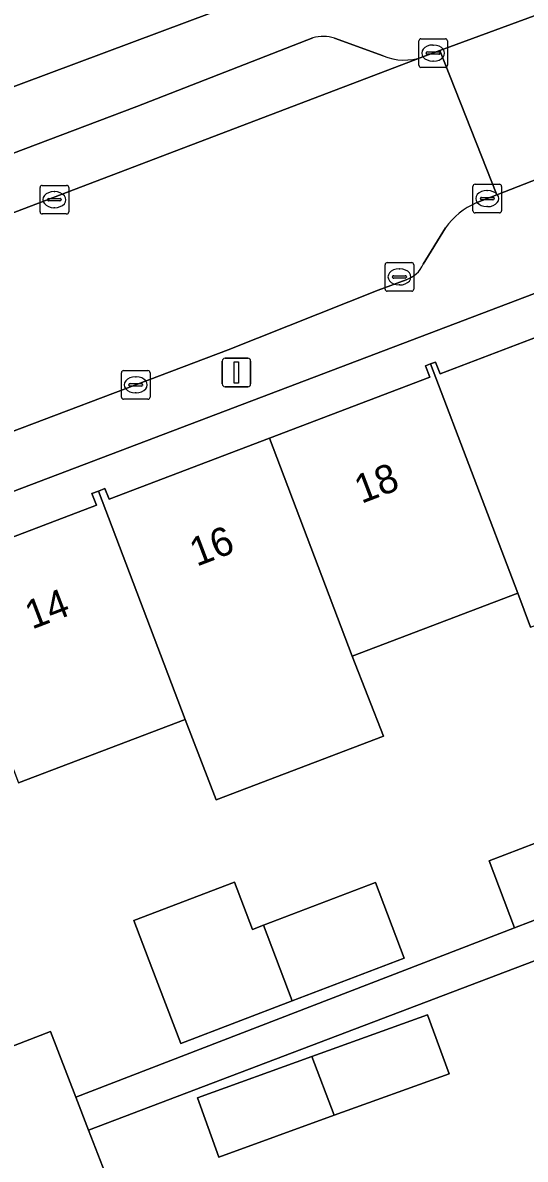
# Model space of a CAD drawing. Extents: x 159262 to 160143, y 383399 to 384319.
# Drawn here: x 159394.93 to 159412.47, y 383870.4 to 383910.07 of the extents above; entities that cross this region are included whole.
import ezdxf

# ---------------------------------------------------------------- set-up
doc = ezdxf.new("R2010")
doc.units = 0
for name, color, linetype in [('IMGEO_Erf', 7, 'Continuous'), ('IMGEO_Kolk', 7, 'Continuous'), ('IMGEO_Lichtmast', 7, 'Continuous'), ('IMGEO_Pand', 7, 'Continuous'), ('IMGEO_Pand_nummerreeks', 7, 'Continuous'), ('IMGEO_Parkeervlak_open', 7, 'Continuous'), ('IMGEO_Rijbaan_lokaal_open', 7, 'Continuous'), ('IMGEO_Voetpad_open', 7, 'Continuous')]:
    doc.layers.add(name, color=color, linetype=linetype)

msp = doc.modelspace()

# ---------------------------------------------------------------- linework, layer by layer
at = {"layer": 'IMGEO_Erf'}
for points in [[(159344.204, 383933.471), (159339.87, 383931.849), (159348.323, 383909.525), (159348.27, 383909.245), (159354.634, 383892.446), (159357.328, 383893.521), (159359.454, 383894.369), (159391.087, 383906.525), (159403.464, 383911.157), (159412.277, 383914.472)], [(159417.717, 383902.495), (159363.447, 383881.885), (159359.686, 383880.457)], [(159391.972, 383873.342), (159395.894, 383874.856), (159396.776, 383872.57), (159412.093, 383878.481), (159411.201, 383880.818), (159415.03, 383882.281), (159414.52, 383883.616), (159420.498, 383885.901), (159421.901, 383882.229), (159426.589, 383884.021), (159421.273, 383900.478)], [(159391.905, 383891.102), (159397.497, 383893.23), (159397.343, 383893.634), (159397.57, 383893.72), (159397.797, 383893.807), (159397.939, 383893.433), (159403.539, 383895.563), (159409.136, 383897.693), (159408.984, 383898.091), (159409.161, 383898.158), (159409.336, 383898.225), (159409.494, 383897.813), (159414.875, 383899.86)], [(159412.653, 383888.968), (159412.203, 383890.152), (159406.429, 383887.958), (159407.518, 383885.163), (159401.676, 383882.943), (159400.601, 383885.744), (159394.782, 383883.533)], [(159433.414, 383862.892), (159427.008, 383882.725), (159397.222, 383871.414), (159397.789, 383869.946), (159393.849, 383868.425)]]:
    msp.add_lwpolyline(points, dxfattribs=at)
for points in [[(159399.434, 383877.085), (159398.808, 383878.731), (159402.319, 383880.066), (159402.945, 383878.42), (159403.329, 383878.566), (159407.235, 383880.052), (159408.24, 383877.411), (159404.333, 383875.925), (159400.439, 383874.443)], [(159405.801, 383871.932), (159401.77, 383870.476), (159401.023, 383872.543), (159405.018, 383873.985), (159409.058, 383875.444), (159409.805, 383873.377)]]:
    msp.add_lwpolyline(points, close=True, dxfattribs=at)
at = {"layer": 'IMGEO_Kolk'}
for p, q in [((159408.75, 383908.582), (159408.75, 383909.434)), ((159408.825, 383909.508), (159409.677, 383909.508)), ((159409.238, 383909.288), (159409.263, 383909.288)), ((159409.751, 383909.434), (159409.751, 383908.582)), ((159409.009, 383909.002), (159409.009, 383909.014)), ((159409.447, 383908.965), (159409.049, 383908.965)), ((159409.052, 383909.051), (159409.45, 383909.051)), ((159409.261, 383908.728), (159409.236, 383908.728)), ((159409.493, 383909.014), (159409.493, 383909.002)), ((159409.677, 383908.508), (159408.825, 383908.508)), ((159395.605, 383904.391), (159396.457, 383904.391)), ((159410.714, 383904.429), (159411.566, 383904.429)), ((159395.53, 383903.465), (159395.53, 383904.317)), ((159396.018, 383904.171), (159396.043, 383904.171)), ((159396.531, 383904.317), (159396.531, 383903.465)), ((159410.639, 383903.503), (159410.639, 383904.355)), ((159410.941, 383903.972), (159411.339, 383903.972)), ((159411.127, 383904.209), (159411.152, 383904.209)), ((159411.64, 383904.355), (159411.64, 383903.503)), ((159395.789, 383903.885), (159395.789, 383903.897)), ((159396.227, 383903.848), (159395.829, 383903.848)), ((159395.832, 383903.934), (159396.23, 383903.934)), ((159396.041, 383903.611), (159396.016, 383903.611)), ((159396.273, 383903.897), (159396.273, 383903.885)), ((159410.898, 383903.923), (159410.898, 383903.935)), ((159411.336, 383903.886), (159410.938, 383903.886)), ((159411.15, 383903.649), (159411.125, 383903.649)), ((159411.382, 383903.935), (159411.382, 383903.923)), ((159396.457, 383903.391), (159395.605, 383903.391)), ((159411.566, 383903.429), (159410.714, 383903.429)), ((159407.574, 383900.768), (159407.574, 383901.62)), ((159407.649, 383901.694), (159408.501, 383901.694)), ((159408.575, 383901.62), (159408.575, 383900.768)), ((159407.833, 383901.188), (159407.833, 383901.2)), ((159407.876, 383901.237), (159408.274, 383901.237)), ((159408.062, 383901.474), (159408.087, 383901.474)), ((159408.317, 383901.2), (159408.317, 383901.188)), ((159408.271, 383901.151), (159407.873, 383901.151)), ((159408.085, 383900.914), (159408.06, 383900.914)), ((159408.501, 383900.694), (159407.649, 383900.694)), ((159398.369, 383897), (159398.369, 383897.852)), ((159398.444, 383897.926), (159399.296, 383897.926)), ((159398.857, 383897.706), (159398.882, 383897.706)), ((159399.37, 383897.852), (159399.37, 383897)), ((159398.628, 383897.42), (159398.628, 383897.432)), ((159399.066, 383897.383), (159398.668, 383897.383)), ((159398.671, 383897.469), (159399.069, 383897.469)), ((159399.112, 383897.432), (159399.112, 383897.42)), ((159399.296, 383896.926), (159398.444, 383896.926)), ((159398.88, 383897.146), (159398.855, 383897.146))]:
    msp.add_line(p, q, dxfattribs=at)
for points in [[(159408.75, 383908.582), (159408.75, 383909.434)], [(159408.825, 383909.508), (159409.677, 383909.508)], [(159409.751, 383909.434), (159409.751, 383908.582)], [(159409.677, 383908.508), (159408.825, 383908.508)], [(159395.605, 383904.391), (159396.457, 383904.391)], [(159410.714, 383904.429), (159411.566, 383904.429)], [(159395.53, 383903.465), (159395.53, 383904.317)], [(159396.531, 383904.317), (159396.531, 383903.465)], [(159410.639, 383903.503), (159410.639, 383904.355)], [(159411.64, 383904.355), (159411.64, 383903.503)], [(159396.457, 383903.391), (159395.605, 383903.391)], [(159411.566, 383903.429), (159410.714, 383903.429)], [(159407.574, 383900.768), (159407.574, 383901.62)], [(159407.649, 383901.694), (159408.501, 383901.694)], [(159408.575, 383901.62), (159408.575, 383900.768)], [(159408.501, 383900.694), (159407.649, 383900.694)], [(159398.369, 383897), (159398.369, 383897.852)], [(159398.444, 383897.926), (159399.296, 383897.926)], [(159399.37, 383897.852), (159399.37, 383897)], [(159399.296, 383896.926), (159398.444, 383896.926)]]:
    msp.add_lwpolyline(points, dxfattribs=at)
for centre, radius, start, end in [((159408.827, 383909.432), 0.0765, 91.552, 178.448), ((159408.827, 383909.432), 0.0765, 91.552, 178.448), ((159409.675, 383909.432), 0.0765, 1.552, 88.448), ((159409.675, 383909.432), 0.0765, 1.552, 88.448), ((159409.049, 383909.011), 0.0403, 85.8775, 175.7526), ((159409.046, 383909.001), 0.0366, 178.938, 274.7102), ((159409.45, 383909.008), 0.043, 264.8664, 352.4533), ((159409.454, 383909.013), 0.0386, 1.7309, 96.639), ((159408.827, 383908.584), 0.0765, 181.552, 268.448), ((159408.827, 383908.584), 0.0765, 181.552, 268.448), ((159409.675, 383908.584), 0.0765, 271.552, 358.448), ((159409.675, 383908.584), 0.0765, 271.552, 358.448), ((159395.607, 383904.315), 0.0765, 91.552, 178.448), ((159395.607, 383904.315), 0.0765, 91.552, 178.448), ((159396.455, 383904.315), 0.0765, 1.552, 88.448), ((159396.455, 383904.315), 0.0765, 1.552, 88.448), ((159410.716, 383904.353), 0.0765, 91.552, 178.448), ((159410.716, 383904.353), 0.0765, 91.552, 178.448), ((159411.564, 383904.353), 0.0765, 1.552, 88.448), ((159411.564, 383904.353), 0.0765, 1.552, 88.448), ((159410.938, 383903.932), 0.0403, 85.8775, 175.7526), ((159411.343, 383903.934), 0.0386, 1.7309, 96.639), ((159395.829, 383903.894), 0.0403, 85.8775, 175.7526), ((159395.826, 383903.884), 0.0366, 178.938, 274.7102), ((159396.23, 383903.891), 0.043, 264.8664, 352.4533), ((159396.234, 383903.896), 0.0386, 1.7309, 96.639), ((159410.935, 383903.922), 0.0366, 178.938, 274.7102), ((159411.339, 383903.929), 0.043, 264.8664, 352.4533), ((159395.607, 383903.467), 0.0765, 181.552, 268.448), ((159395.607, 383903.467), 0.0765, 181.552, 268.448), ((159396.455, 383903.467), 0.0765, 271.552, 358.448), ((159396.455, 383903.467), 0.0765, 271.552, 358.448), ((159410.716, 383903.505), 0.0765, 181.552, 268.448), ((159410.716, 383903.505), 0.0765, 181.552, 268.448), ((159411.564, 383903.505), 0.0765, 271.552, 358.448), ((159411.564, 383903.505), 0.0765, 271.552, 358.448), ((159407.651, 383901.618), 0.0765, 91.552, 178.448), ((159407.651, 383901.618), 0.0765, 91.552, 178.448), ((159408.499, 383901.618), 0.0765, 1.552, 88.448), ((159408.499, 383901.618), 0.0765, 1.552, 88.448), ((159407.873, 383901.197), 0.0403, 85.8775, 175.7526), ((159408.278, 383901.199), 0.0386, 1.7309, 96.639), ((159407.87, 383901.187), 0.0366, 178.938, 274.7102), ((159408.274, 383901.194), 0.043, 264.8664, 352.4533), ((159407.651, 383900.77), 0.0765, 181.552, 268.448), ((159407.651, 383900.77), 0.0765, 181.552, 268.448), ((159408.499, 383900.77), 0.0765, 271.552, 358.448), ((159408.499, 383900.77), 0.0765, 271.552, 358.448), ((159398.446, 383897.85), 0.0765, 91.552, 178.448), ((159398.446, 383897.85), 0.0765, 91.552, 178.448), ((159399.294, 383897.85), 0.0765, 1.552, 88.448), ((159399.294, 383897.85), 0.0765, 1.552, 88.448), ((159398.668, 383897.429), 0.0403, 85.8775, 175.7526), ((159398.665, 383897.419), 0.0366, 178.938, 274.7102), ((159399.069, 383897.426), 0.043, 264.8664, 352.4533), ((159399.073, 383897.431), 0.0386, 1.7309, 96.639), ((159398.446, 383897.002), 0.0765, 181.552, 268.448), ((159398.446, 383897.002), 0.0765, 181.552, 268.448), ((159399.294, 383897.002), 0.0765, 271.552, 358.448), ((159399.294, 383897.002), 0.0765, 271.552, 358.448)]:
    msp.add_arc(centre, radius, start, end, dxfattribs=at)
for centre, major_axis, ratio, start_param, end_param in [((159409.237, 383909.008), (-0.387, 0.002), 0.722429, 4.712389, 7.853982), ((159409.262, 383909.008), (-0.39, 0.002), 0.717154, 1.570796, 4.712389), ((159396.017, 383903.891), (-0.387, 0.002), 0.722429, 4.712389, 7.853982), ((159396.042, 383903.891), (-0.39, 0.002), 0.717154, 1.570796, 4.712389), ((159411.126, 383903.929), (-0.387, 0.002), 0.722429, 4.712389, 7.853982), ((159411.151, 383903.929), (-0.39, 0.002), 0.717154, 1.570796, 4.712389), ((159408.061, 383901.194), (-0.387, 0.002), 0.722429, 4.712389, 7.853982), ((159408.086, 383901.194), (-0.39, 0.002), 0.717154, 1.570796, 4.712389), ((159398.856, 383897.426), (-0.387, 0.002), 0.722429, 4.712389, 7.853982), ((159398.881, 383897.426), (-0.39, 0.002), 0.717154, 1.570796, 4.712389)]:
    msp.add_ellipse(centre, major_axis=major_axis, ratio=ratio, start_param=start_param, end_param=end_param, dxfattribs=at)
at = {"layer": 'IMGEO_Lichtmast'}
for p, q in [((159401.889, 383897.459), (159401.889, 383898.259)), ((159401.889, 383898.259), (159401.889, 383897.459)), ((159401.989, 383898.359), (159402.779, 383898.359)), ((159402.779, 383898.359), (159401.989, 383898.359)), ((159402.879, 383898.259), (159402.879, 383897.459)), ((159402.879, 383897.459), (159402.879, 383898.259)), ((159402.779, 383897.359), (159401.989, 383897.359)), ((159401.989, 383897.359), (159402.779, 383897.359))]:
    msp.add_line(p, q, dxfattribs=at)
msp.add_lwpolyline([(159402.309, 383898.234), (159402.459, 383898.234), (159402.459, 383897.484), (159402.309, 383897.484), (159402.309, 383898.234)], dxfattribs=at)
for centre, start, end in [((159401.989, 383898.259), 90, 180), ((159401.989, 383898.259), 90, 180), ((159402.779, 383898.259), 0, 90), ((159402.779, 383898.259), 360, 90), ((159401.989, 383897.459), 180, 270), ((159401.989, 383897.459), 180, 270), ((159402.779, 383897.459), 270, 0), ((159402.779, 383897.459), 270, 0)]:
    msp.add_arc(centre, 0.1, start, end, dxfattribs=at)
at = {"layer": 'IMGEO_Pand'}
for points in [[(159421.549, 383898.8), (159416.481, 383896.757), (159415.085, 383900.425), (159414.714, 383900.284), (159414.875, 383899.86), (159409.494, 383897.813), (159409.336, 383898.225), (159409.161, 383898.158), (159412.203, 383890.152), (159412.653, 383888.968), (159423.436, 383893.014)], [(159406.429, 383887.958), (159412.203, 383890.152), (159409.161, 383898.158), (159408.984, 383898.091), (159409.136, 383897.693), (159403.539, 383895.563)], [(159403.539, 383895.563), (159397.939, 383893.433), (159397.797, 383893.807), (159397.57, 383893.72), (159400.601, 383885.744), (159401.676, 383882.943), (159407.518, 383885.163), (159406.429, 383887.958)], [(159400.601, 383885.744), (159397.57, 383893.72), (159397.343, 383893.634), (159397.497, 383893.23), (159391.905, 383891.102), (159394.782, 383883.533)], [(159415.03, 383882.281), (159411.201, 383880.818), (159412.093, 383878.481), (159415.922, 383879.944)], [(159403.329, 383878.566), (159402.945, 383878.42), (159402.319, 383880.066), (159398.808, 383878.731), (159399.434, 383877.085), (159400.439, 383874.443), (159404.333, 383875.925)], [(159403.329, 383878.566), (159404.333, 383875.925), (159408.24, 383877.411), (159407.235, 383880.052)], [(159405.801, 383871.932), (159409.805, 383873.377), (159409.058, 383875.444), (159405.018, 383873.985)], [(159396.776, 383872.57), (159395.894, 383874.856), (159391.972, 383873.342), (159393.849, 383868.425), (159397.789, 383869.946), (159397.222, 383871.414)], [(159405.801, 383871.932), (159405.018, 383873.985), (159401.023, 383872.543), (159401.77, 383870.476)]]:
    msp.add_lwpolyline(points, close=True, dxfattribs=at)
at = {"layer": 'IMGEO_Parkeervlak_open'}
for points in [[(159405.054, 383909.537), (159398.907, 383907.143), (159364.612, 383894.169), (159363.675, 383893.818)], [(159407.504, 383908.911), (159405.812, 383909.528)], [(159360.29, 383890.372), (159408.89, 383908.872)]]:
    msp.add_lwpolyline(points, dxfattribs=at)
for centre, radius, start, end in [((159405.418, 383908.266), 1.322, 72.6564, 105.9831), ((159408.249, 383910.726), 1.962, 247.6965, 289.0799)]:
    msp.add_arc(centre, radius, start, end, dxfattribs=at)
at = {"layer": 'IMGEO_Rijbaan_lokaal_open'}
for points in [[(159414.708, 383911.033), (159409.489, 383909.098), (159411.474, 383904.062), (159414.605, 383905.276)], [(159410.756, 383903.776), (159411.474, 383904.062), (159409.489, 383909.098), (159408.89, 383908.872), (159360.29, 383890.372), (159362.763, 383883.722), (159369.522, 383886.236), (159373.965, 383887.945), (159380.876, 383890.636), (159392.067, 383894.857), (159402.096, 383898.646)], [(159408.903, 383901.635), (159409.683, 383902.906)], [(159402.096, 383898.646), (159407.335, 383900.738), (159408.31, 383901.097)]]:
    msp.add_lwpolyline(points, dxfattribs=at)
for centre, radius, start, end in [((159411.725, 383901.484), 2.489, 112.9224, 145.1487), ((159407.976, 383902.061), 1.021, 289.1204, 335.3114)]:
    msp.add_arc(centre, radius, start, end, dxfattribs=at)
at = {"layer": 'IMGEO_Voetpad_open'}
for points in [[(159412.277, 383914.472), (159403.464, 383911.157), (159391.087, 383906.525), (159359.454, 383894.369), (159357.328, 383893.521), (159354.634, 383892.446), (159352.307, 383891.408)], [(159408.89, 383908.872), (159409.489, 383909.098), (159414.708, 383911.033)], [(159363.675, 383893.818), (159364.612, 383894.169), (159398.907, 383907.143), (159405.054, 383909.537)], [(159405.812, 383909.528), (159407.504, 383908.911)], [(159414.605, 383905.276), (159411.474, 383904.062), (159410.756, 383903.776)], [(159409.683, 383902.906), (159408.903, 383901.635)], [(159408.31, 383901.097), (159407.335, 383900.738), (159402.096, 383898.646), (159392.067, 383894.857), (159380.876, 383890.636), (159373.965, 383887.945), (159369.522, 383886.236), (159362.763, 383883.722), (159363.447, 383881.885), (159417.717, 383902.495)]]:
    msp.add_lwpolyline(points, dxfattribs=at)
msp.add_lwpolyline([(159427.008, 383882.725), (159426.589, 383884.021), (159421.901, 383882.229), (159415.922, 383879.944), (159412.093, 383878.481), (159396.776, 383872.57), (159397.222, 383871.414)], close=True, dxfattribs=at)
for centre, radius, start, end in [((159405.418, 383908.266), 1.322, 72.6564, 105.9831), ((159408.249, 383910.726), 1.962, 247.6965, 289.0799), ((159411.725, 383901.484), 2.489, 112.9224, 145.1487), ((159407.976, 383902.061), 1.021, 289.1204, 335.3114)]:
    msp.add_arc(centre, radius, start, end, dxfattribs=at)

# ---------------------------------------------------------------- texts
at = {"layer": 'IMGEO_Pand_nummerreeks'}
for s, p in [('18', (159406.747, 383893.271)), ('16', (159400.996, 383891.076)), ('14', (159395.248, 383888.882))]:
    msp.add_text(s, height=1, rotation=20.8903, dxfattribs=at).set_placement(p)

doc.saveas('drawing.dxf')
